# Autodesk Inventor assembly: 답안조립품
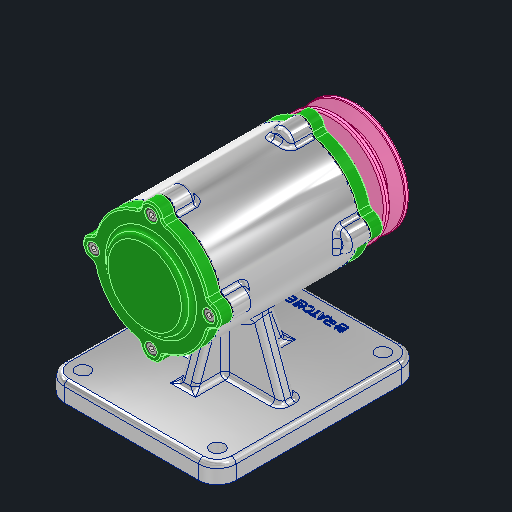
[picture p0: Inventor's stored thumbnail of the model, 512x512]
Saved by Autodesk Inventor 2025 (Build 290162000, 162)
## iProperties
Created: 2025-08
Part Number: 답안조립품
Document SubType Name: Assembly
Designer: infra08
Author: infra08
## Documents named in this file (12)
- C:\Users\infra08\Desktop\750806V1007\답안조립품.iam
- C:\Users\infra08\Desktop\750806V1007\본체.ipt
- C:\Users\infra08\Desktop\750806V1007\V-벨트풀리\V-벨트풀리.ipt
- C:\Users\infra08\Desktop\750806V1007\개스킷\개스킷.ipt
- C:\Users\infra08\Desktop\750806V1007\너트 M12 x 1.25\너트 M12 x 1.25.ipt
- C:\Users\infra08\Desktop\750806V1007\뒤커버\뒤커버.ipt
- C:\Users\infra08\Desktop\750806V1007\베어링 6204\베어링 6204.ipt
- C:\Users\infra08\Desktop\750806V1007\볼트 M4 x 12\볼트 M4 x 12.ipt
- C:\Users\infra08\Desktop\750806V1007\앞커버\앞커버.ipt
- C:\Users\infra08\Desktop\750806V1007\오일 실\오일 실.ipt
- C:\Users\infra08\Desktop\750806V1007\축\축.ipt
- C:\Users\infra08\Desktop\750806V1007\키 4 x 4\키 4 x 4.ipt
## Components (3 placed, 2 different names)
1. V-벨트풀리:1
2. 개스킷:1
3. 개스킷:2
